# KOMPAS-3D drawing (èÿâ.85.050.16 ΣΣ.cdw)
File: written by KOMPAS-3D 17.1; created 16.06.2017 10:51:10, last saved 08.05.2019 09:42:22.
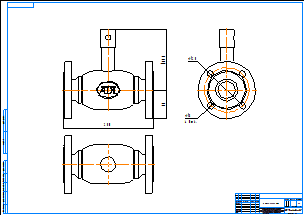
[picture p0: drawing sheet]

Sheet 1: A1, landscape

Title block, sheet 1: name: КШГ.85.050.16 фф; material: Внимание! Данный продукт является объектом авторского права ООО «Торговый Дом АДЛ». / Запрещается изменение, копирование, распространение / (в том числе путем копирования на другие сайты и ресурсы в Интернете) / или любое иное использование информации и объектов без предварительного / согласия правообладателя (ООО «Торговый Дом АДЛ»).; scale: 1:1; sheets: 1; organisation: ООО "Торговый дом АДЛ"; sheet format: A1; stored path: C:\Users\tra\Desktop\2д чертежи\Шаровые краны БИВАЛ\КШ_Бивал_серия_82_85\KOMPAS 2D\КШГ.85.050.16 фф.cdw

Views: Спереди 1, Проекционный вид 2, Проекционный вид 3
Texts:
  Klimkovich
  ADL
Dimensions and other numbers on the sheet: 250; 167,3; 80; 125; 18; 4 Отв.; 1:1; 1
